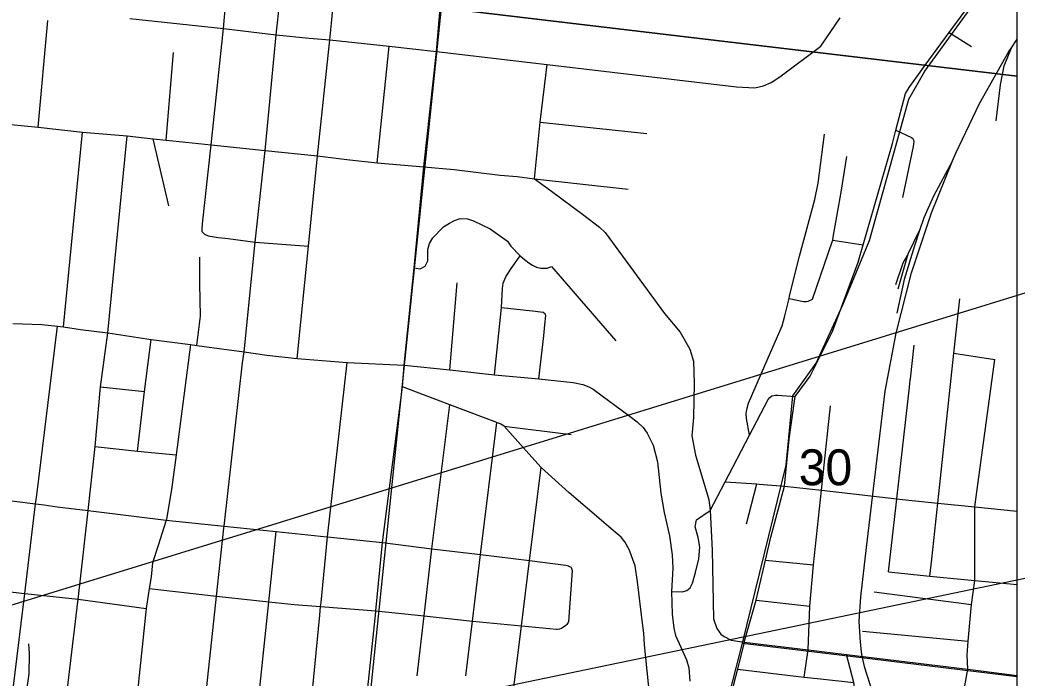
# Model space of a CAD drawing. Extents: x 0 to 34, y -2 to 22.
# Drawn here: x 7.738 to 8.9, y 16.694 to 17.461 of the extents above; entities that cross this region are included whole.
import ezdxf

# ---------------------------------------------------------------- set-up
doc = ezdxf.new("R2010")
doc.units = 0
for name, color, linetype in [('Default', 7, 'Continuous'), ('GM_X_City_Street', 7, 'Continuous'), ('GM_X_County_Road', 7, 'Continuous'), ('GM_X_Minor_River', 7, 'Continuous'), ('GM_X_Rail_Line', 7, 'Continuous'), ('GM_X_Section', 7, 'Continuous'), ('GM_X_Section_Text', 7, 'Continuous'), ('GM_X_State_Route', 7, 'Continuous'), ('SH_Cut_Line', 7, 'Continuous'), ('SH_Data', 7, 'Continuous')]:
    doc.layers.add(name, color=color, linetype=linetype)

msp = doc.modelspace()

# ---------------------------------------------------------------- linework, layer by layer
at = {"layer": 'Default'}
for points in [[(8.9, 17.3957), (8.9, 18.4149), (8.3344, 18.4751), (8.2288, 17.4754)], [(8.9, 16.3966), (8.9, 17.3957), (8.2288, 17.4754), (8.1243, 16.4653), (8.7506, 16.3888), (8.762, 16.3912), (8.7711, 16.3925), (8.792, 16.3947), (8.8076, 16.3958), (8.8333, 16.3964), (8.8504, 16.3971), (8.8879, 16.3966)]]:
    msp.add_lwpolyline(points, close=True, dxfattribs=at)
at = {"layer": 'GM_X_City_Street'}
for p, q in [((7.7594, 17.3362), (7.7705, 17.4604)), ((8.8207, 17.4464), (8.8469, 17.4302)), ((8.1543, 17.2946), (8.1682, 17.4307)), ((7.9084, 17.321), (7.9171, 17.4233)), ((8.3444, 17.3422), (8.4685, 17.3289)), ((7.7889, 17.1033), (7.8111, 17.3304)), ((7.9116, 17.2444), (7.8931, 17.3225)), ((8.3377, 17.2758), (8.4468, 17.264)), ((8.6852, 17.2046), (8.7208, 17.199)), ((8.2391, 17.0532), (8.2476, 17.1549)), ((8.8262, 17.0726), (8.8742, 17.0655)), ((7.832, 17.0335), (7.8833, 17.0281)), ((8.3025, 16.9878), (8.3804, 16.9778)), ((8.5599, 16.9229), (8.5966, 16.9203)), ((8.5846, 16.874), (8.5966, 16.9203)), ((8.6067, 16.8315), (8.6628, 16.8261)), ((8.7333, 16.7946), (8.8469, 16.7798)), ((8.5958, 16.7847), (8.6586, 16.7777)), ((8.7199, 16.7486), (8.843, 16.7372))]:
    msp.add_line(p, q, dxfattribs=at)
for points in [[(7.9504, 17.2143), (7.9504, 17.2176), (7.9509, 17.2234), (7.9607, 17.3157), (7.9752, 17.4513), (7.9806, 17.5136), (7.9813, 17.529), (7.9823, 17.5376), (7.9835, 17.5428), (7.9858, 17.551)], [(8.0612, 17.0667), (8.0744, 17.1973), (8.0848, 17.3028), (8.0991, 17.438), (8.101, 17.4576), (8.1025, 17.4738), (8.103, 17.4777), (8.1031, 17.4832), (8.1031, 17.4872), (8.1038, 17.4894), (8.1054, 17.4898)], [(7.976, 16.871), (7.9973, 17.0616), (7.9992, 17.0743), (8.012, 17.2021), (8.0237, 17.3088), (8.0365, 17.4437), (8.041, 17.4827)], [(7.866, 17.4629), (7.9752, 17.4513), (8.0365, 17.4437), (8.075, 17.4399), (8.0991, 17.438), (8.1682, 17.4307), (8.2234, 17.4245), (8.3525, 17.4091), (8.5731, 17.3832), (8.5944, 17.3821), (8.6046, 17.3845), (8.6134, 17.3882), (8.6236, 17.395), (8.6715, 17.4307), (8.6939, 17.4636)], [(8.3377, 17.2758), (8.3444, 17.3422), (8.3525, 17.4091)], [(7.7649, 16.4449), (7.806, 16.7861), (7.8078, 16.8027), (7.8174, 16.8895), (7.8255, 16.9639), (7.832, 17.0335), (7.8404, 17.0964), (7.863, 17.3259)], [(8.5882, 16.9772), (8.5848, 16.9965), (8.5842, 17.0023), (8.5851, 17.0072), (8.5871, 17.0144), (8.6062, 17.0585), (8.6261, 17.1046), (8.6294, 17.1163), (8.6343, 17.1363), (8.635, 17.1394), (8.6464, 17.1857), (8.6644, 17.2517), (8.6682, 17.271), (8.6755, 17.3281)], [(8.7589, 17.3326), (8.7771, 17.324), (8.7784, 17.3228), (8.7792, 17.3216), (8.7796, 17.3198), (8.7794, 17.3162), (8.779, 17.3137), (8.7664, 17.2541)], [(8.6616, 17.1357), (8.685, 17.2035), (8.6852, 17.2046), (8.6858, 17.2081), (8.691, 17.2386), (8.6948, 17.2579), (8.7018, 17.3021)], [(8.1973, 17.1724), (8.2045, 17.1711), (8.2104, 17.1743), (8.2133, 17.1802), (8.2133, 17.1936), (8.2154, 17.2007), (8.2191, 17.2071), (8.2316, 17.2199), (8.2385, 17.2244), (8.2443, 17.2275), (8.2509, 17.2298), (8.2596, 17.2294), (8.2667, 17.2269), (8.2859, 17.2175), (8.3062, 17.2032), (8.3102, 17.1973), (8.3211, 17.1864), (8.326, 17.1819), (8.331, 17.1782), (8.3354, 17.1755), (8.34, 17.1729), (8.345, 17.1717), (8.3523, 17.172), (8.3574, 17.1736), (8.4326, 17.087)], [(7.9504, 17.2143), (7.9531, 17.2115), (7.9574, 17.2097), (7.9692, 17.2074), (7.9806, 17.2065), (8.012, 17.2021), (8.0744, 17.1973)], [(8.2912, 17.0475), (8.2992, 17.126), (8.3003, 17.1481), (8.301, 17.1545), (8.3044, 17.1617), (8.3104, 17.1714), (8.3211, 17.1864)], [(7.9443, 17.0818), (7.9483, 17.1158), (7.9478, 17.154), (7.9476, 17.1846)], [(8.6343, 17.1363), (8.6513, 17.1329), (8.6541, 17.1328), (8.6566, 17.1332), (8.6616, 17.1357)], [(8.7985, 16.813), (8.8006, 16.8326), (8.8075, 16.8979), (8.8262, 17.0726), (8.8332, 17.1362)], [(8.2992, 17.126), (8.339, 17.1216), (8.3475, 17.1205)], [(8.3428, 17.0427), (8.3484, 17.0929), (8.3497, 17.1058), (8.3507, 17.1165), (8.3501, 17.1183), (8.3475, 17.1205)], [(7.8749, 16.9584), (7.8833, 17.0281), (7.8909, 17.0887)], [(8.7756, 17.0418), (8.7758, 17.0428), (8.7802, 17.0819)], [(8.0875, 16.7675), (8.0884, 16.7774), (8.0889, 16.7823), (8.0964, 16.8585), (8.1194, 17.0619)], [(8.8509, 16.8839), (8.8509, 16.8935), (8.8525, 16.9052), (8.8742, 17.0655)], [(8.7501, 16.8178), (8.759, 16.896), (8.7598, 16.9029), (8.7746, 17.033), (8.7756, 17.0418)], [(8.5424, 16.8895), (8.5599, 16.9229), (8.5882, 16.9772), (8.6099, 17.0188), (8.612, 17.021), (8.6142, 17.0229), (8.6184, 17.0238), (8.621, 17.0239), (8.6414, 17.0222)], [(8.2009, 16.6968), (8.2089, 16.7664), (8.2181, 16.8448), (8.2388, 17.0125)], [(8.6518, 16.6951), (8.6564, 16.7269), (8.6586, 16.7777), (8.6628, 16.8261), (8.672, 16.913), (8.6825, 17.0115)], [(8.2578, 16.6968), (8.2654, 16.7603), (8.2746, 16.8379), (8.2938, 16.9919)], [(7.8255, 16.9639), (7.8749, 16.9584), (7.9199, 16.9541)], [(8.249, 16.2935), (8.2588, 16.3226), (8.2687, 16.3568), (8.2748, 16.3824), (8.2944, 16.5277), (8.3135, 16.6831), (8.3224, 16.7549), (8.3317, 16.831), (8.3455, 16.9395)], [(8.5966, 16.9203), (8.5994, 16.9201), (8.6291, 16.9179)], [(7.7069, 16.9033), (7.7563, 16.8973), (7.7663, 16.8959)], [(7.7663, 16.8959), (7.7813, 16.8937), (7.8174, 16.8895), (7.9084, 16.878), (7.976, 16.871), (8.0368, 16.8647), (8.0956, 16.8586), (8.0964, 16.8585), (8.1605, 16.8519), (8.2181, 16.8448), (8.2746, 16.8379), (8.3317, 16.831), (8.3743, 16.8258), (8.3774, 16.8249), (8.3786, 16.8242), (8.3803, 16.8233)], [(8.8518, 16.5076), (8.8525, 16.5139), (8.8549, 16.5371), (8.8549, 16.553), (8.8531, 16.5658), (8.8352, 16.6374), (8.8331, 16.6464), (8.8343, 16.6591), (8.8425, 16.7043), (8.8419, 16.7208), (8.843, 16.7372), (8.8469, 16.7798), (8.8508, 16.8078), (8.8509, 16.8839)], [(7.9288, 16.4279), (7.9525, 16.6517), (7.9671, 16.7897), (7.9757, 16.8689), (7.976, 16.871)], [(7.9683, 16.2129), (7.9807, 16.3308), (7.9902, 16.4215), (8.0138, 16.6456), (8.0282, 16.783), (8.0368, 16.8647)], [(8.3743, 16.7556), (8.3762, 16.7571), (8.377, 16.7585), (8.3775, 16.76), (8.382, 16.8191), (8.3813, 16.8212), (8.3803, 16.8233)], [(8.7501, 16.8178), (8.7985, 16.813), (8.8384, 16.8091), (8.8508, 16.8078), (8.9, 16.803)], [(8.0293, 16.2079), (8.0415, 16.3234), (8.0512, 16.4151), (8.0749, 16.6394), (8.0875, 16.7675)], [(8.0808, 16.1002), (8.0907, 16.1902), (8.092, 16.2027), (8.1081, 16.3502), (8.1138, 16.4023), (8.1157, 16.4203), (8.1285, 16.5421), (8.1381, 16.6331), (8.1402, 16.6531), (8.1526, 16.7714), (8.1527, 16.7724)], [(8.1527, 16.7724), (8.2089, 16.7664), (8.2654, 16.7603), (8.3224, 16.7549), (8.3632, 16.751), (8.3643, 16.751), (8.3671, 16.7516), (8.3692, 16.7523), (8.3743, 16.7556)], [(8.6949, 16.4961), (8.6983, 16.527), (8.7042, 16.5799), (8.7134, 16.6613), (8.7097, 16.6888), (8.7012, 16.7217)], [(8.5741, 16.7044), (8.6518, 16.6951), (8.6711, 16.693), (8.7097, 16.6888)]]:
    msp.add_lwpolyline(points, dxfattribs=at)
at = {"layer": 'GM_X_County_Road'}
for p, q in [((7.8888, 16.7983), (7.8851, 16.7752)), ((8.8425, 16.7043), (8.9, 16.6972))]:
    msp.add_line(p, q, dxfattribs=at)
for points in [[(8.582, 16.7358), (8.5958, 16.7847), (8.6067, 16.8315), (8.613, 16.8584), (8.6291, 16.9179), (8.6344, 16.9724), (8.6414, 17.0222), (8.6589, 17.0461), (8.685, 17.0981), (8.715, 17.1789), (8.7208, 17.199), (8.755, 17.3171), (8.7589, 17.3326), (8.7699, 17.3755), (8.7743, 17.3825), (8.7929, 17.4086), (8.8207, 17.4464), (8.9, 17.5541)], [(8.1527, 16.7724), (8.1605, 16.8519), (8.1839, 17.0337), (8.1856, 17.0588), (8.1973, 17.1724), (8.2088, 17.2899), (8.2234, 17.4245), (8.228, 17.4791)], [(7.7299, 17.1075), (7.7634, 17.1063), (7.7817, 17.1042), (7.7889, 17.1033), (7.8084, 17.1004), (7.8404, 17.0964), (7.8909, 17.0887), (7.9366, 17.0828), (7.9443, 17.0818), (7.9992, 17.0743), (8.0259, 17.0705), (8.0612, 17.0667), (8.1194, 17.0619), (8.1856, 17.0588)], [(7.7576, 16.9073), (7.7602, 16.9261), (7.7817, 17.1042)], [(7.9366, 17.0828), (7.9199, 16.9541), (7.915, 16.9167), (7.9087, 16.8789), (7.9084, 16.878), (7.8992, 16.8485), (7.8926, 16.8282), (7.891, 16.8119), (7.8888, 16.7983)], [(8.1856, 17.0588), (8.2391, 17.0532), (8.2912, 17.0475), (8.3428, 17.0427), (8.3828, 17.0386), (8.3941, 17.0363), (8.401, 17.0335), (8.406, 17.0309), (8.4492, 16.999), (8.4574, 16.9927), (8.4642, 16.9861), (8.4688, 16.9796), (8.476, 16.9656), (8.481, 16.9462), (8.485, 16.9094), (8.4888, 16.8872), (8.495, 16.8597), (8.4981, 16.8376), (8.4987, 16.8222), (8.4975, 16.7951), (8.4979, 16.7686), (8.4999, 16.7522), (8.5021, 16.7436), (8.508, 16.73), (8.5147, 16.7154), (8.5176, 16.7061), (8.5186, 16.6903)], [(8.3312, 16.9556), (8.3025, 16.9878), (8.2984, 16.9901), (8.2938, 16.9919), (8.2388, 17.0125), (8.1839, 17.0337)], [(8.4127, 16.8804), (8.3779, 16.9101), (8.3455, 16.9395), (8.3312, 16.9556)], [(7.4637, 15.9561), (7.4964, 16.0209), (7.5352, 16.0954), (7.5404, 16.1047), (7.558, 16.1266), (7.6348, 16.2084), (7.6443, 16.2237), (7.6522, 16.2368), (7.6565, 16.247), (7.6579, 16.2514), (7.6603, 16.2699), (7.6794, 16.4469), (7.6823, 16.4535), (7.6835, 16.4563), (7.6891, 16.469), (7.7056, 16.5046), (7.7084, 16.5106), (7.7098, 16.5193), (7.7437, 16.7928), (7.7563, 16.8973), (7.7576, 16.9073)], [(8.6291, 16.9179), (8.672, 16.913), (8.7598, 16.9029), (8.7665, 16.9021), (8.8075, 16.8979), (8.8509, 16.8935), (8.9, 16.8884)], [(8.4975, 16.7951), (8.51, 16.7944), (8.5153, 16.796), (8.5192, 16.7991), (8.5219, 16.8045), (8.5253, 16.8172), (8.5293, 16.8332), (8.5304, 16.8467), (8.5284, 16.8579), (8.5248, 16.8704), (8.5263, 16.8783), (8.5424, 16.8895)], [(8.4634, 16.7581), (8.4575, 16.8062), (8.4549, 16.8247), (8.4481, 16.8439), (8.443, 16.8527), (8.4386, 16.8581), (8.4271, 16.8681), (8.4127, 16.8804)], [(7.4025, 16.8396), (7.4054, 16.8392), (7.4318, 16.8345), (7.4767, 16.8251), (7.5074, 16.8201), (7.5322, 16.8169), (7.5671, 16.8129), (7.6305, 16.8061), (7.6888, 16.7991), (7.6957, 16.7979), (7.7437, 16.7928), (7.806, 16.7861), (7.8851, 16.7752)], [(7.8888, 16.7983), (7.9671, 16.7897), (8.0282, 16.783), (8.0575, 16.7798), (8.0884, 16.7774), (8.1527, 16.7724)], [(7.8851, 16.7752), (7.8729, 16.6597)], [(8.496, 16.4413), (8.4951, 16.4428), (8.4944, 16.4442), (8.4933, 16.4463), (8.4929, 16.4471), (8.4924, 16.4479), (8.4919, 16.4495), (8.4916, 16.4503), (8.4913, 16.451), (8.4912, 16.4528), (8.4909, 16.4569), (8.4909, 16.4609), (8.4896, 16.4823), (8.4878, 16.5107), (8.4856, 16.5485), (8.4767, 16.6269), (8.466, 16.7328), (8.4649, 16.7463), (8.4634, 16.7581)], [(8.582, 16.7358), (8.6564, 16.7269), (8.7012, 16.7217), (8.8425, 16.7043)]]:
    msp.add_lwpolyline(points, dxfattribs=at)
at = {"layer": 'GM_X_Minor_River'}
msp.add_lwpolyline([(7.748, 16.7339), (7.7489, 16.7225), (7.7484, 16.6989), (7.7466, 16.6853), (7.7448, 16.6713), (7.7429, 16.6565), (7.7406, 16.6391), (7.7388, 16.6266), (7.7374, 16.6141), (7.7357, 16.6035), (7.7335, 16.5936), (7.7314, 16.5808), (7.7293, 16.5709), (7.7255, 16.5573), (7.7218, 16.5437), (7.7145, 16.5234), (7.7063, 16.5095), (7.6996, 16.4998), (7.691, 16.4863), (7.6816, 16.4728), (7.6744, 16.4581), (7.6681, 16.4453)], dxfattribs=at)
at = {"layer": 'GM_X_Rail_Line'}
for p, q in [((8.8934, 17.4287), (8.9, 17.4387)), ((8.7732, 17.1884), (8.7865, 17.2159)), ((8.7614, 17.1479), (8.7732, 17.1884)), ((8.5802, 16.7346), (8.7157, 16.7184)), ((8.7157, 16.7184), (8.9, 16.6958))]:
    msp.add_line(p, q, dxfattribs=at)
for points in [[(7.6912, 15.289), (7.9856, 15.5639), (8.2003, 15.8586), (8.2596, 15.9572), (8.5337, 16.2495), (8.6286, 16.3042), (8.7283, 16.3459), (8.827, 16.358), (8.9, 16.3574), (8.9, 20.9)], [(8.5802, 16.7346), (8.6309, 16.9422), (8.6388, 17.023), (8.6657, 17.0611), (8.697, 17.129), (8.7281, 17.2039), (8.7533, 17.2946), (8.7737, 17.3687), (8.7924, 17.4016), (8.9, 17.55)], [(8.8249, 17.2971), (8.8285, 17.306), (8.8562, 17.3637), (8.8904, 17.4242), (8.8934, 17.4287)], [(8.8756, 17.3435), (8.8807, 17.3856), (8.8849, 17.4078), (8.8934, 17.4287)], [(8.7301, 16.6829), (8.7243, 16.7008), (8.7223, 16.7077), (8.7206, 16.7146), (8.7193, 16.7216), (8.7183, 16.7287), (8.7176, 16.7358), (8.7161, 16.7598), (8.7178, 16.7889), (8.7247, 16.8461), (8.7462, 17.0284), (8.7592, 17.0962), (8.7768, 17.1662), (8.8002, 17.2365), (8.8249, 17.2971)], [(8.8249, 17.2971), (8.8026, 17.2559), (8.7912, 17.2305), (8.7865, 17.2159)], [(8.7865, 17.2159), (8.7806, 17.1977), (8.7683, 17.1588), (8.7599, 17.1193)], [(8.7732, 17.1884), (8.767, 17.1775), (8.7582, 17.1524)], [(7.6638, 15.5316), (7.8133, 15.5592), (7.8376, 15.5732), (7.9564, 15.6556), (8.0387, 15.7554), (8.1052, 15.8663), (8.1195, 15.9107), (8.1527, 15.9329), (8.2366, 16.0359), (8.3506, 16.1959), (8.5517, 16.4051), (8.5526, 16.406), (8.556, 16.4117), (8.5563, 16.418), (8.5292, 16.4485), (8.5216, 16.4764), (8.5242, 16.5167), (8.5802, 16.7346)]]:
    msp.add_lwpolyline(points, dxfattribs=at)
at = {"layer": 'GM_X_Section'}
msp.add_lwpolyline([(7.2505, 17.5778), (8.2288, 17.4754), (8.1243, 16.4653), (7.1499, 16.5781)], close=True, dxfattribs=at)
at = {"layer": 'GM_X_State_Route'}
for points in [[(7.7274, 17.3393), (7.7594, 17.3362), (7.8111, 17.3304), (7.863, 17.3259), (7.8931, 17.3225), (7.9084, 17.321), (7.9314, 17.3186), (7.9607, 17.3157), (8.0237, 17.3088), (8.0848, 17.3028), (8.1188, 17.2986), (8.1543, 17.2946), (8.2088, 17.2899), (8.244, 17.2867), (8.2977, 17.2804), (8.3173, 17.2785), (8.3377, 17.2758), (8.3573, 17.2614), (8.3952, 17.2337), (8.4134, 17.2195), (8.4201, 17.2136), (8.4892, 17.119), (8.5075, 17.0973), (8.5187, 17.0775), (8.5231, 17.0636), (8.5237, 17.0373), (8.523, 16.9978), (8.5209, 16.9763), (8.5251, 16.954), (8.5407, 16.902), (8.5424, 16.8895), (8.5448, 16.8432), (8.5464, 16.763), (8.5501, 16.7519), (8.5547, 16.7454), (8.5588, 16.7424), (8.5669, 16.7384), (8.582, 16.7358)], [(8.582, 16.7358), (8.5741, 16.7044), (8.5668, 16.676), (8.5566, 16.6345), (8.5462, 16.598), (8.5335, 16.5449), (8.5302, 16.535), (8.5296, 16.5332)]]:
    msp.add_lwpolyline(points, dxfattribs=at)
at = {"layer": 'SH_Cut_Line'}
msp.add_lwpolyline([(6.0485, 14.702), (6.1464, 14.7771), (6.2416, 14.8366), (6.3391, 14.8719), (6.8207, 14.994), (7.0052, 15.0295), (7.018, 15.0319), (7.3068, 15.0956), (7.4995, 15.1593), (7.5948, 15.214), (7.6912, 15.289), (7.9856, 15.5639), (8.2003, 15.8586), (8.2596, 15.9572), (8.5337, 16.2495), (8.6286, 16.3042), (8.7283, 16.3459), (8.827, 16.358), (8.9, 16.3574), (8.9, 20.9), (2.1, 20.9)], dxfattribs=at)
at = {"layer": 'SH_Data'}
msp.add_lwpolyline([(5.5739, 16.1159), (9.9248, 17.4558), (9.9244, 17.0214)], close=True, dxfattribs=at)

# ---------------------------------------------------------------- texts
at = {"layer": 'GM_X_Section_Text'}
msp.add_text('30', height=0.04186, rotation=0, dxfattribs=at).set_placement((8.6456, 16.9188))

doc.saveas('drawing.dxf')
